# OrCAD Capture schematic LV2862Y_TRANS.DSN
size E; title: LV2862Y High Efficiency Wide Input Voltage Range Buck; rev: 1.0; note: DATASHEET: SNVSA49  EVM:NA
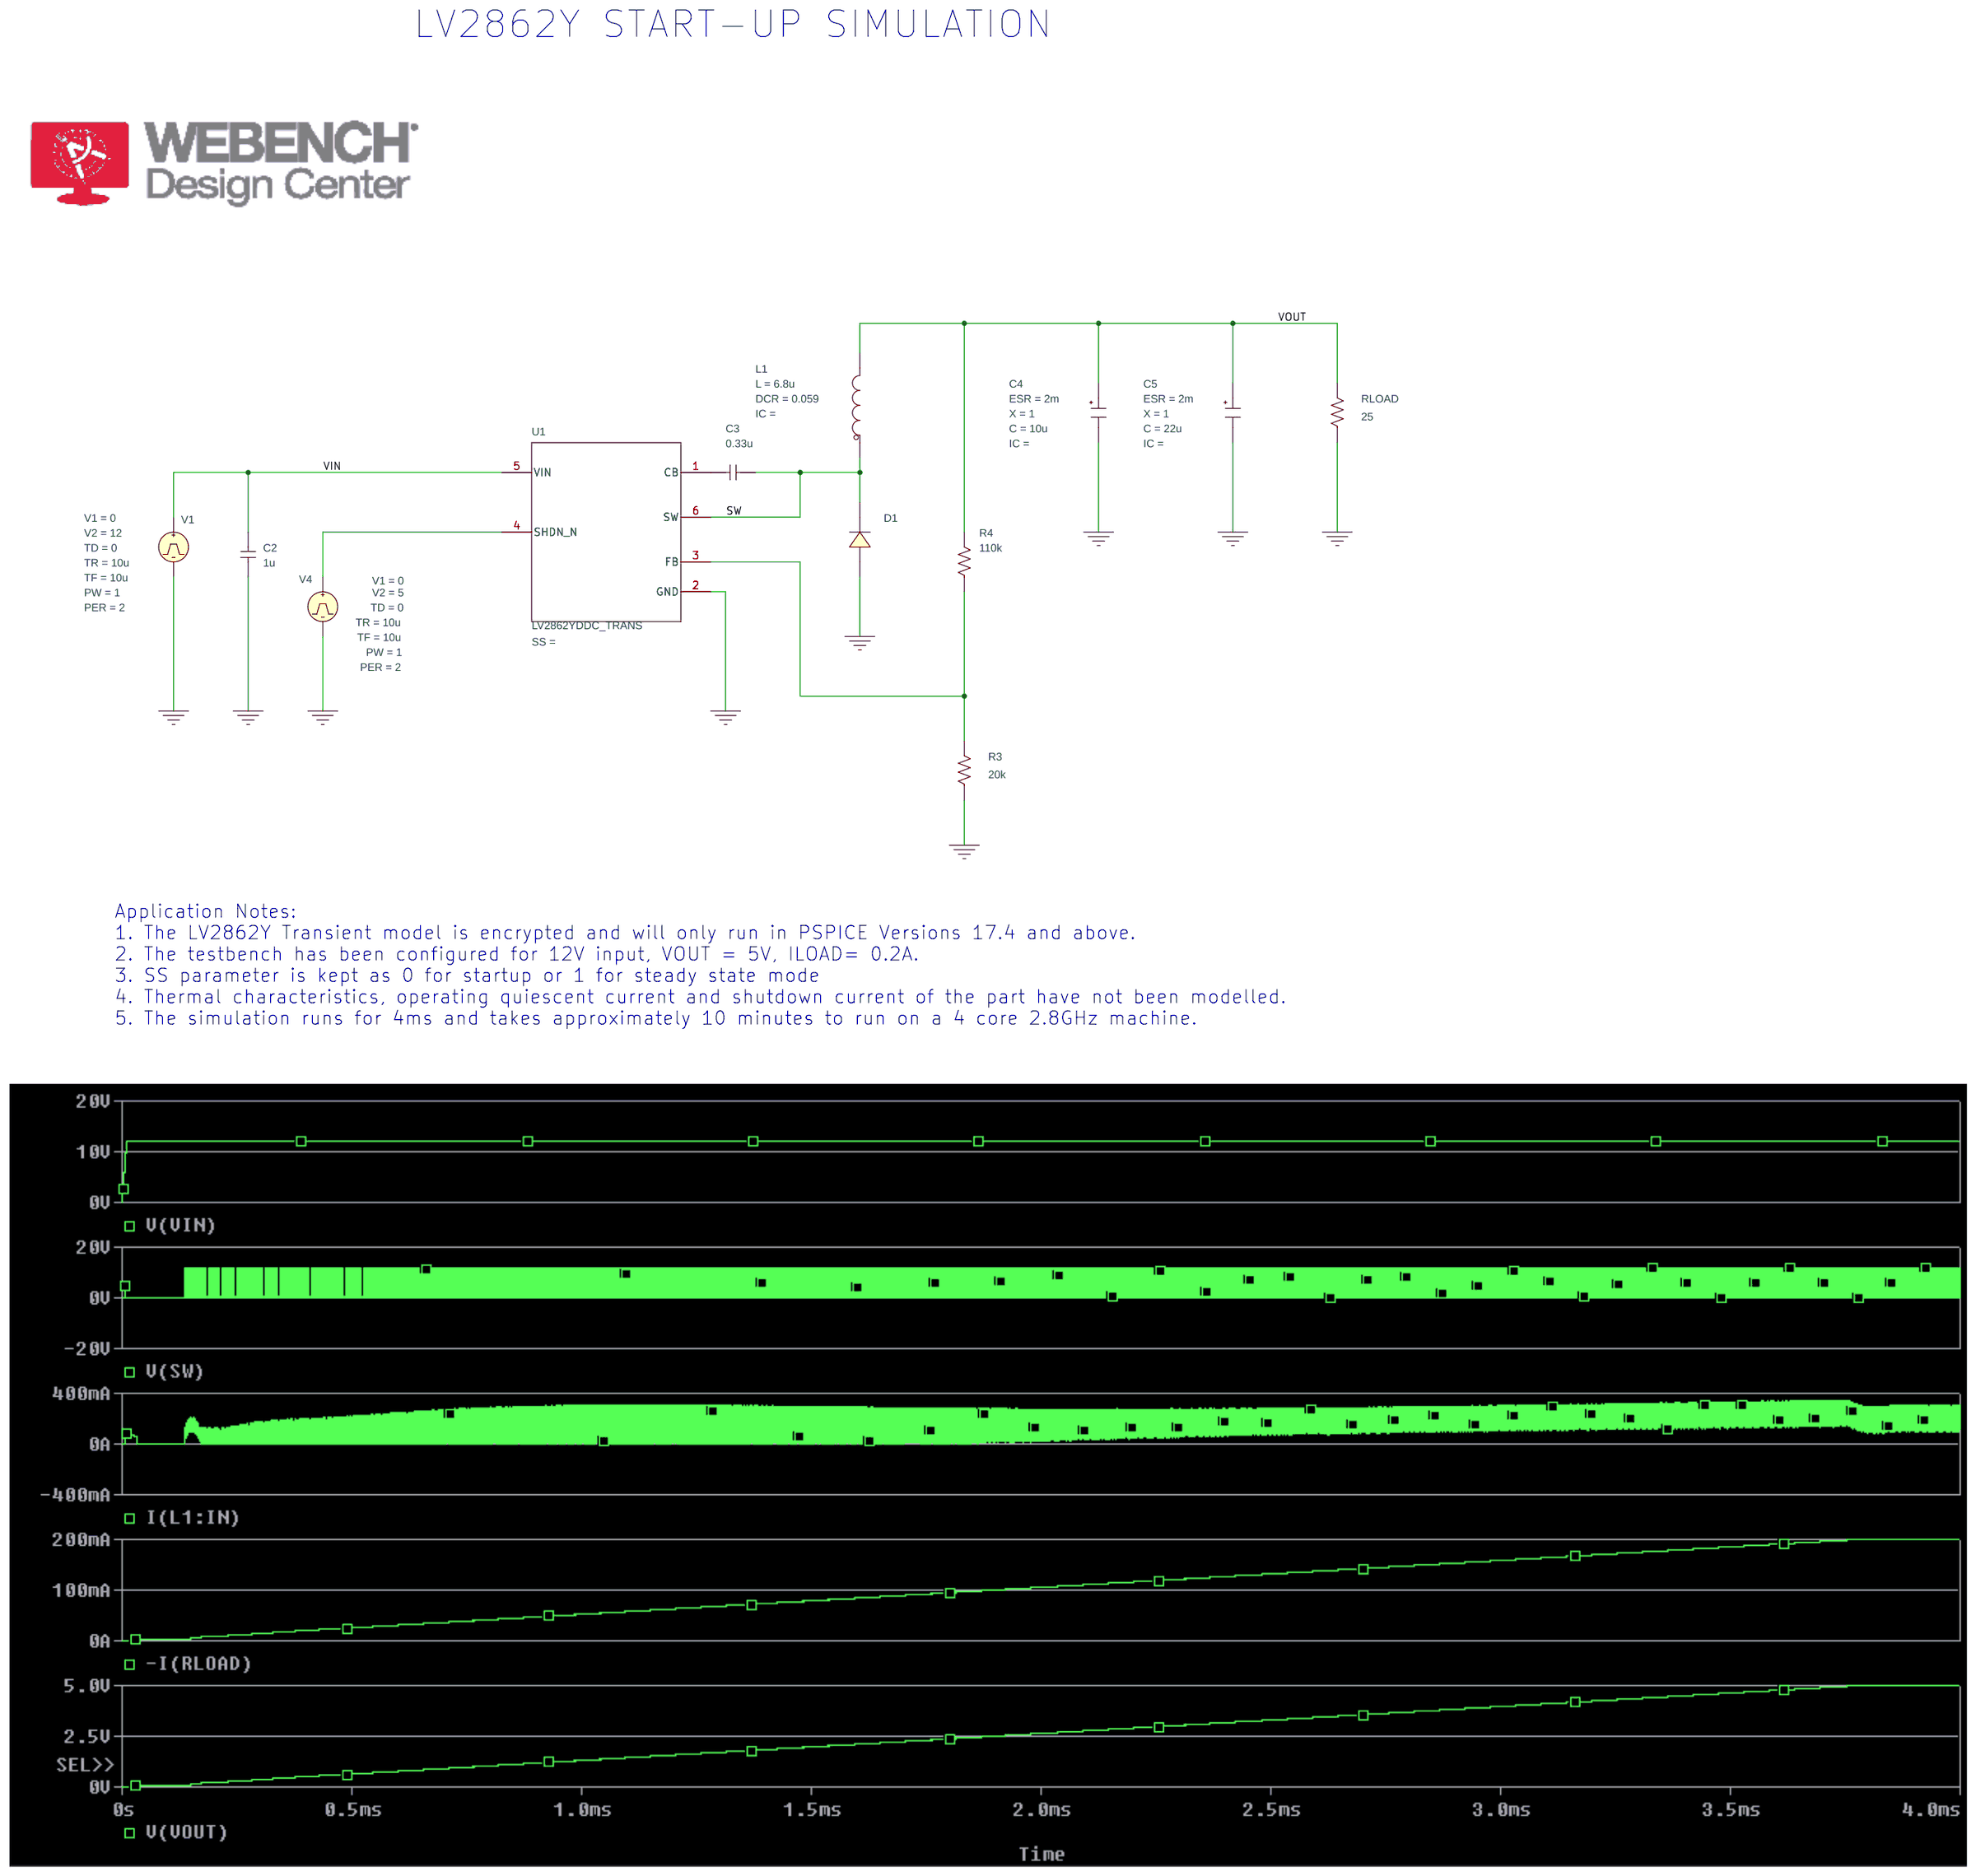
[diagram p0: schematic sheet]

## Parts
C2  1u  [RAD/CK05]
C3  0.33u  [RAD/CK05]
C4  CESR
C5  CESR
D1  D_D1
L1  LDCR
R3  20k  [AX/RC05]
R4  110k  [AX/RC05]
RLOAD  25  [AX/RC05]
U1  LV2862YDDC_TRANS  [DDC0006A-IPC_A]
V1  VPULSE
V4  VPULSE

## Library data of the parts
C2 C3 = C
C4 = CESR_0: C: 10u; ESR: 2m; PSpiceTemplate: X^@REFDES %IN %OUT @MODEL PARAMS:  ?C|C=@C||C=100u|  ?ESR|ESR=@ESR||ESR=0.01| ?X|X=@X||X=2|  ?IC|IC=@IC||IC=2|; X: 1
C5 = CESR_0: C: 22u; ESR: 2m; PSpiceTemplate: X^@REFDES %IN %OUT @MODEL PARAMS:  ?C|C=@C||C=100u|  ?ESR|ESR=@ESR||ESR=0.01| ?X|X=@X||X=2|  ?IC|IC=@IC||IC=2|; X: 1
D1 = D_D1
L1 = LDCR_0: DCR: 0.059; L: 6.8u; PSpiceTemplate: X^@REFDES %IN %OUT @MODEL PARAMS:  ?L|L=@L||L=1u|  ?DCR|DCR=@DCR||DCR=0.01| ?IC|IC=@IC||IC=0|
R3 R4 RLOAD = R
U1 = LV2862YDDC_TRANS
V1 = VPULSE: PER: 2; PW: 1; TD: 0; TF: 10u; TR: 10u; V1: 0; V2: 12
V4 = VPULSE: PER: 2; PW: 1; TD: 0; TF: 10u; TR: 10u; V1: 0; V2: 5

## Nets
VIN: C2.2 U1.5(VIN) V1.1(+)
0: C2.1 C4.3(OUT) C5.3(OUT) D1.2(A) R3.1 RLOAD.1 U1.2(GND) V1.2(-) V4.2(-)
SW: C3.1 D1.1(C) L1.1(IN) U1.6(SW)
VOUT: C4.1(IN) C5.1(IN) L1.3(OUT) R4.2 RLOAD.2
N16325964: U1.4(SHDN_N) V4.1(+)
N16325968: R3.2 R4.1 U1.3(FB)
N16331133: C3.2 U1.1(CB)

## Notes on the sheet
- LV2862Y START-UP SIMULATION
- Application Notes:
  1. The LV2862Y Transient model is encrypted and will only run in PSPICE Versions 17.4 and above.
  2. The testbench has been configured for 12V input, VOUT = 5V, ILOAD= 0.2A.
  3. SS parameter is kept as 0 for startup or 1 for steady state mode
  4. Thermal characteristics, operating quiescent current and shutdown current of the part have not been modelled.
  5. The simulation runs for 4ms and takes approximately 10 minutes to run on a 4 core 2.8GHz machine.
